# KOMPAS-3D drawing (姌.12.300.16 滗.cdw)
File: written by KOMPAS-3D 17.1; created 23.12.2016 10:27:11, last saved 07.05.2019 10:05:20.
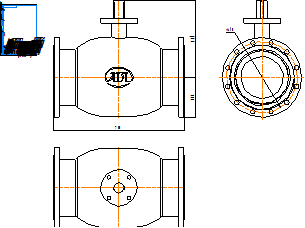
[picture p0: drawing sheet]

Sheet 1: A4, portrait

Title block, sheet 1: name: КШ.12.300.16 фф; material: Внимание! Данный продукт является объектом авторского права ООО «Торговый Дом АДЛ». / Запрещается изменение, копирование, распространение / (в том числе путем копирования на другие сайты и ресурсы в Интернете) / или любое иное использование информации и объектов без предварительного / согласия правообладателя (ООО «Торговый Дом АДЛ»).; sheets: 1; organisation: ООО "Торговый дом АДЛ"; sheet format: A4; stored path: C:\Users\tra\Desktop\2д чертежи\Шаровые краны БИВАЛ\КШ_Бивал_серия_11_12\KOMPAS_2D\КШ.12.300.16 фф.cdw

Views: Вид 1, Проекционный вид 2, Проекционный вид 3
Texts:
  Klimkovich
  ADL
Dimensions and other numbers on the sheet: 750; 441; 230; 410; 1:1; 1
